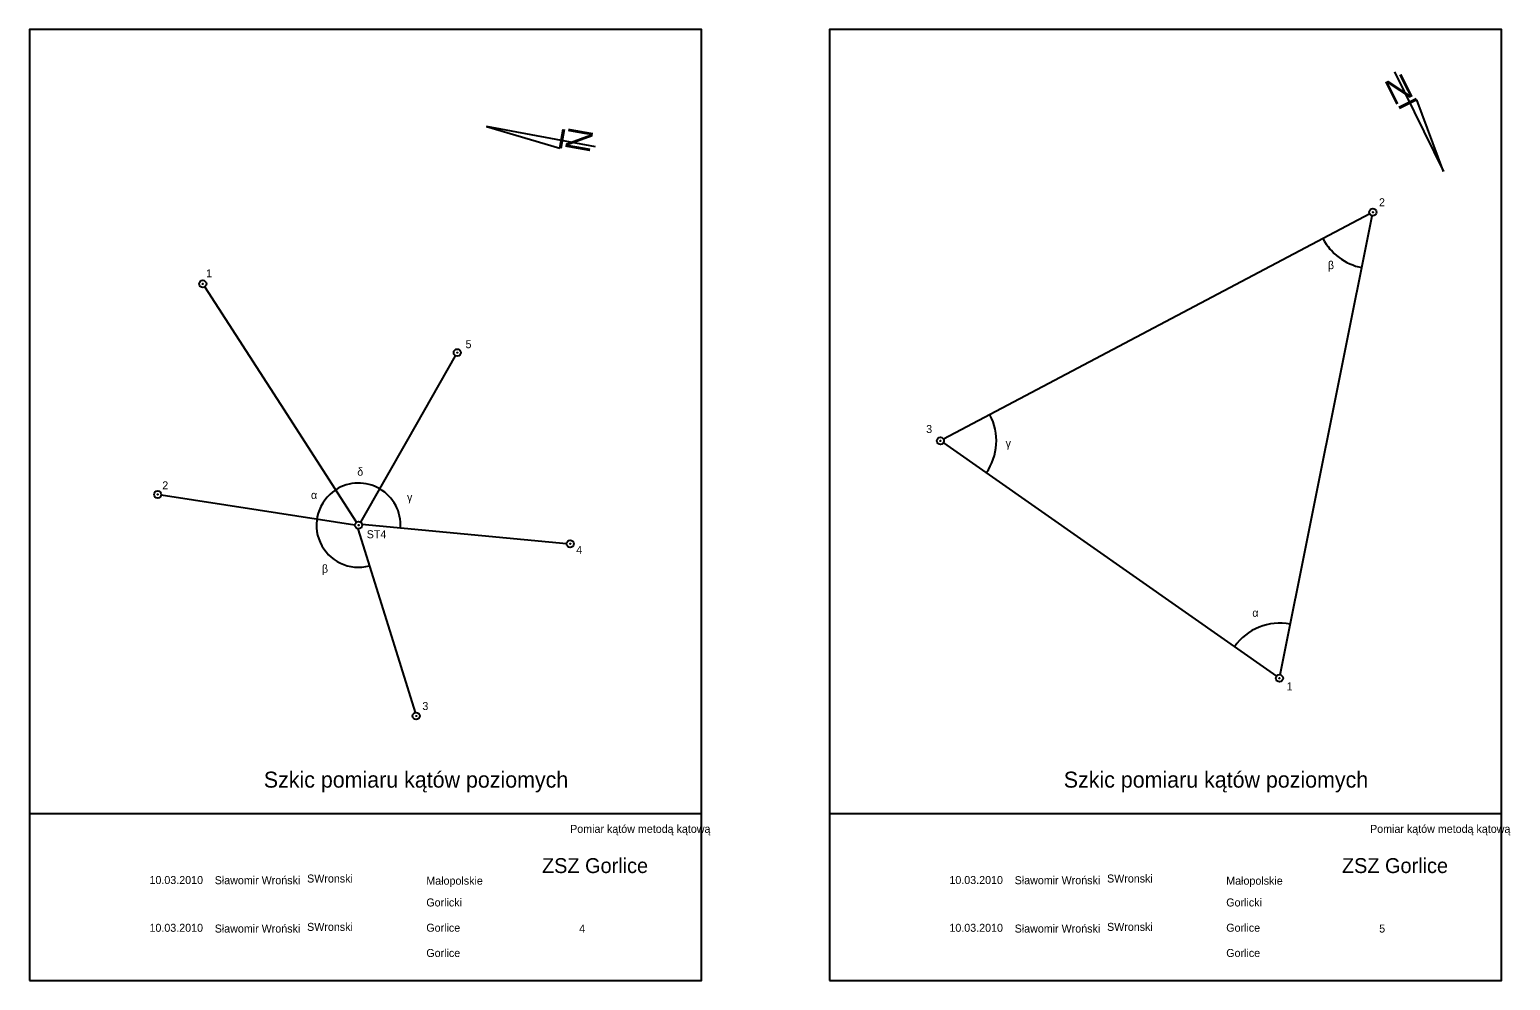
# Model space of a CAD drawing. Extents: x 4638556 to 4639783, y 5351940 to 5352237.
# Drawn here: x 4639320.6 to 4639783.3, y 5351939.6 to 5352236.6 of the extents above; entities that cross this region are included whole.
import ezdxf

# ---------------------------------------------------------------- set-up
doc = ezdxf.new("R2010")
doc.units = 0
doc.layers.add('Default', color=7, linetype='Continuous')

msp = doc.modelspace()

# ---------------------------------------------------------------- linework, layer by layer
at = {"layer": 'Default'}
for p, q in [((4639747.14, 5352223.41), (4639762.39, 5352192.3)), ((4639753.89, 5352215.02), (4639748.5, 5352212.33)), ((4639754.12, 5352214.65), (4639748.73, 5352211.96)), ((4639762.39, 5352192.3), (4639754.12, 5352214.65)), ((4639497.48, 5352200), (4639463.42, 5352206.34)), ((4639463.42, 5352206.34), (4639486.28, 5352199.63)), ((4639486.28, 5352199.63), (4639487.34, 5352205.56)), ((4639486.72, 5352199.6), (4639487.77, 5352205.53)), ((4639399.06, 5352119.5), (4639375.33, 5352156.25)), ((4639438.88, 5352108.72), (4639453.7, 5352134.74)), ((4639422.78, 5352082.75), (4639399.06, 5352119.5)), ((4639424.07, 5352082.7), (4639438.88, 5352108.72)), ((4639392, 5352086.52), (4639361.72, 5352091.23)), ((4639422.27, 5352081.82), (4639392, 5352086.52)), ((4639423.21, 5352080.71), (4639432.15, 5352051.99)), ((4639424.46, 5352082.12), (4639456.44, 5352079.11)), ((4639456.44, 5352079.11), (4639488.42, 5352076.09)), ((4639432.15, 5352051.99), (4639441.09, 5352023.27))]:
    msp.add_line(p, q, dxfattribs=at)
for points in [[(4639320.6, 5351939.61), (4639530.6, 5351939.61), (4639530.6, 5352236.61), (4639320.6, 5352236.61)], [(4639570.58, 5351939.61), (4639780.58, 5351939.61), (4639780.58, 5352236.61), (4639570.58, 5352236.61)], [(4639320.6, 5351939.61), (4639530.6, 5351939.61), (4639530.6, 5351991.61), (4639320.6, 5351991.61)], [(4639570.58, 5351939.61), (4639780.58, 5351939.61), (4639780.58, 5351991.61), (4639570.58, 5351991.61)]]:
    msp.add_lwpolyline(points, close=True, dxfattribs=at)
for points in [[(4639739.37, 5352179.06), (4639606.21, 5352108.67)], [(4639711.39, 5352035.1), (4639740.14, 5352178.48)], [(4639606.14, 5352107.5), (4639710.26, 5352034.64)]]:
    msp.add_lwpolyline(points, dxfattribs=at)
for centre, radius in [((4639740.36, 5352179.58), 1.12), ((4639740.36, 5352179.58), 0.0804), ((4639374.72, 5352157.19), 1.12), ((4639374.72, 5352157.19), 0.0804), ((4639454.25, 5352135.71), 1.12), ((4639454.25, 5352135.71), 0.0804), ((4639605.22, 5352108.14), 1.12), ((4639605.22, 5352108.14), 0.0804), ((4639360.62, 5352091.4), 1.12), ((4639360.62, 5352091.4), 0.0804), ((4639423.39, 5352081.81), 1.12), ((4639423.39, 5352081.81), 0.0804), ((4639489.54, 5352075.99), 1.12), ((4639489.54, 5352075.99), 0.0804), ((4639711.17, 5352034), 1.12), ((4639711.17, 5352034), 0.0804), ((4639441.42, 5352022.2), 1.12), ((4639441.42, 5352022.2), 0.0804)]:
    msp.add_circle(centre, radius, dxfattribs=at)
for centre, radius, start, end in [((4639740.36, 5352179.58), 17.66, 207.8607, 258.6615), ((4639605.22, 5352108.14), 17.48, 325.017, 27.8607), ((4639423.39, 5352081.81), 13.15, 356.4168, 122.8465), ((4639423.39, 5352081.81), 13.15, 122.8465, 285.1224), ((4639711.17, 5352034), 17.19, 78.6615, 145.017)]:
    msp.add_arc(centre, radius, start, end, dxfattribs=at)

# ---------------------------------------------------------------- texts
for rotation, p in [(206.5625, (4639750.1, 5352223.17)), (79.9131, (4639495.52, 5352197.77))]:
    msp.add_text('N', height=7.81, rotation=rotation, dxfattribs=at).set_placement(p)
for s, height, p in [('2', 2.5, (4639742.27, 5352181.44)), ('β', 2.5, (4639726.29, 5352161.8)), ('1', 2.5, (4639375.76, 5352159.23)), ('5', 2.5, (4639456.83, 5352137.09)), ('3', 2.5, (4639600.77, 5352110.6)), ('γ', 2.5, (4639625.6, 5352106.17)), ('δ', 2.5, (4639423, 5352097.27)), ('2', 2.5, (4639362.06, 5352093)), ('α', 2.5, (4639408.53, 5352089.99)), ('γ', 2.5, (4639438.54, 5352089.34)), ('ST4', 2.5, (4639425.94, 5352077.72)), ('4', 2.5, (4639491.41, 5352072.83)), ('β', 2.5, (4639411.93, 5352066.97)), ('α', 2.5, (4639702.69, 5352053.19)), ('1', 2.5, (4639713.38, 5352030.19)), ('3', 2.5, (4639443.33, 5352024.06)), ('Szkic pomiaru kątów poziomych', 5, (4639393.79, 5351999.82)), ('Szkic pomiaru kątów poziomych', 5, (4639643.77, 5351999.82)), ('Pomiar kątów metodą kątową', 2.5, (4639489.51, 5351985.69)), ('Pomiar kątów metodą kątową', 2.5, (4639739.48, 5351985.69)), ('ZSZ Gorlice', 4.6473, (4639480.72, 5351973.14)), ('ZSZ Gorlice', 4.6473, (4639730.69, 5351973.14)), ('10.03.2010', 2.5, (4639358.06, 5351969.71)), ('Sławomir Wroński', 2.5, (4639378.44, 5351969.65)), ('SWronski', 2.5, (4639407.32, 5351970.18)), ('Małopolskie', 2.5, (4639444.57, 5351969.5)), ('10.03.2010', 2.5, (4639608.03, 5351969.71)), ('Sławomir Wroński', 2.5, (4639628.42, 5351969.65)), ('SWronski', 2.5, (4639657.29, 5351970.18)), ('Małopolskie', 2.5, (4639694.54, 5351969.5)), ('Gorlicki', 2.5, (4639444.57, 5351962.7)), ('Gorlicki', 2.5, (4639694.54, 5351962.7)), ('10.03.2010', 2.5, (4639358.06, 5351954.79)), ('Sławomir Wroński', 2.5, (4639378.44, 5351954.55)), ('SWronski', 2.5, (4639407.32, 5351955.08)), ('Gorlice', 2.5, (4639444.57, 5351954.81)), ('4', 2.5, (4639492.35, 5351954.55)), ('10.03.2010', 2.5, (4639608.03, 5351954.79)), ('Sławomir Wroński', 2.5, (4639628.42, 5351954.55)), ('SWronski', 2.5, (4639657.29, 5351955.08)), ('Gorlice', 2.5, (4639694.54, 5351954.81)), ('5', 2.5, (4639742.33, 5351954.55)), ('Gorlice', 2.5, (4639444.57, 5351946.92)), ('Gorlice', 2.5, (4639694.54, 5351946.92))]:
    msp.add_text(s, height=height, dxfattribs=at).set_placement(p)

doc.saveas('drawing.dxf')
